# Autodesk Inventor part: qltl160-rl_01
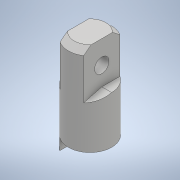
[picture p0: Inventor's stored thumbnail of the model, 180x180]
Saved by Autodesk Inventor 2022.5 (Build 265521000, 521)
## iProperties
Part Number: qltl160-rl_01
Material: 一般
Document SubType Name: Modeling
Designer: ImaoCorp
Density: 1 g/cm^3
Appearance: 既定
Author: ImaoCorp
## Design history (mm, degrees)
feature "qltl160-rl_01"
node "ソリッド1"
